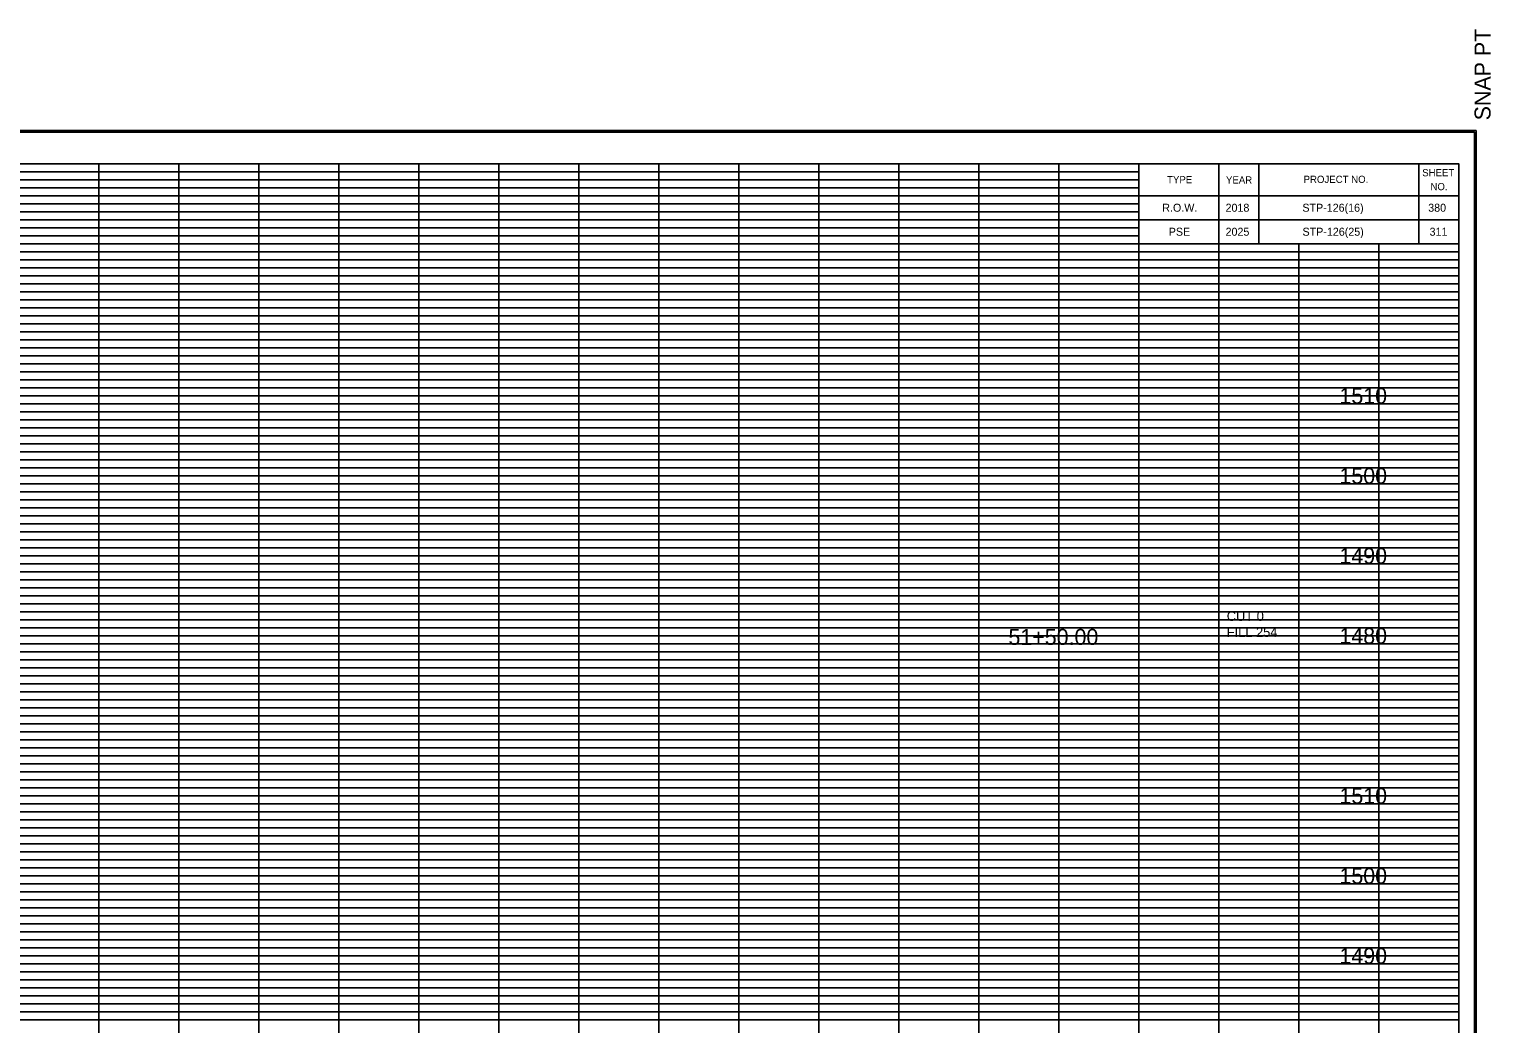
# Model space of a CAD drawing. Extents: x 980 to 1324, y 978 to 1497.
# Drawn here: x 1141.3 to 1324, y 1102.5 to 1226.8 of the extents above; entities that cross this region are included whole.
import ezdxf

# ---------------------------------------------------------------- set-up
doc = ezdxf.new("R2010")
doc.units = 0
for name, color, linetype in [('DESIGN - SCRATCH - User 1', 7, 'Continuous'), ('DESIGN - SHEET - Corner Text', 7, 'Continuous'), ('DESIGN - SHEET - Light Grid', 7, 'Continuous'), ('DESIGN - SHEET - Linework', 7, 'Continuous'), ('DESIGN - SHEET - Plot Shape', 7, 'Continuous'), ('DESIGN - TYPICAL - Text', 7, 'Continuous')]:
    doc.layers.add(name, color=color, linetype=linetype)

# ---------------------------------------------------------------- blocks, each defined once
blk = doc.blocks.new('XSTSHT')
at = {"layer": 'DESIGN - SCRATCH - User 1'}
for p, q in [((28.5, 20.45), (28.5, 20.45)), ((29.24, 20.45), (29.24, 20.45)), ((30.49, 20.45), (30.49, 20.45)), ((31.74, 20.45), (31.74, 20.45)), ((28.5, 20.15), (28.5, 20.15)), ((29.24, 20.15), (29.24, 20.15)), ((30.49, 20.15), (30.49, 20.15)), ((31.74, 20.15), (31.74, 20.15))]:
    blk.add_line(p, q, dxfattribs=at)
at = {"layer": 'DESIGN - SHEET - Light Grid'}
for p, q in [((8, 20.9), (16, 20.9)), ((16, 20.9), (24, 20.9)), ((24, 20.9), (28, 20.9)), ((8, 20.8), (16, 20.8)), ((8, 20.7), (16, 20.7)), ((16, 20.8), (24, 20.8)), ((16, 20.7), (24, 20.7)), ((24, 20.8), (28, 20.8)), ((24, 20.7), (28, 20.7)), ((8, 20.6), (16, 20.6)), ((8, 20.5), (16, 20.5)), ((16, 20.6), (24, 20.6)), ((16, 20.5), (24, 20.5)), ((24, 20.6), (28, 20.6)), ((24, 20.5), (28, 20.5)), ((8, 20.4), (16, 20.4)), ((8, 20.3), (16, 20.3)), ((16, 20.4), (24, 20.4)), ((16, 20.3), (24, 20.3)), ((24, 20.4), (28, 20.4)), ((24, 20.3), (28, 20.3)), ((8, 20.2), (16, 20.2)), ((8, 20.1), (16, 20.1)), ((16, 20.2), (24, 20.2)), ((16, 20.1), (24, 20.1)), ((24, 20.2), (28, 20.2)), ((24, 20.1), (28, 20.1)), ((8, 19.9), (16, 19.9)), ((8, 19.8), (16, 19.8)), ((16, 19.9), (24, 19.9)), ((16, 19.8), (24, 19.8)), ((24, 19.9), (32, 19.9)), ((24, 19.8), (32, 19.8)), ((8, 19.7), (16, 19.7)), ((8, 19.6), (16, 19.6)), ((16, 19.7), (24, 19.7)), ((16, 19.6), (24, 19.6)), ((24, 19.7), (32, 19.7)), ((24, 19.6), (32, 19.6)), ((8, 19.5), (16, 19.5)), ((8, 19.4), (16, 19.4)), ((16, 19.5), (24, 19.5)), ((16, 19.4), (24, 19.4)), ((24, 19.5), (32, 19.5)), ((24, 19.4), (32, 19.4)), ((8, 19.3), (16, 19.3)), ((8, 19.2), (16, 19.2)), ((16, 19.3), (24, 19.3)), ((16, 19.2), (24, 19.2)), ((24, 19.3), (32, 19.3)), ((24, 19.2), (32, 19.2)), ((8, 19.1), (16, 19.1)), ((16, 19.1), (24, 19.1)), ((24, 19.1), (32, 19.1)), ((8, 18.9), (16, 18.9)), ((16, 18.9), (24, 18.9)), ((24, 18.9), (32, 18.9)), ((8, 18.8), (16, 18.8)), ((8, 18.7), (16, 18.7)), ((16, 18.8), (24, 18.8)), ((16, 18.7), (24, 18.7)), ((24, 18.8), (32, 18.8)), ((24, 18.7), (32, 18.7)), ((8, 18.6), (16, 18.6)), ((8, 18.5), (16, 18.5)), ((16, 18.6), (24, 18.6)), ((16, 18.5), (24, 18.5)), ((24, 18.6), (32, 18.6)), ((24, 18.5), (32, 18.5)), ((8, 18.4), (16, 18.4)), ((8, 18.3), (16, 18.3)), ((16, 18.4), (24, 18.4)), ((16, 18.3), (24, 18.3)), ((24, 18.4), (32, 18.4)), ((24, 18.3), (32, 18.3)), ((8, 18.2), (16, 18.2)), ((8, 18.1), (16, 18.1)), ((16, 18.2), (24, 18.2)), ((16, 18.1), (24, 18.1)), ((24, 18.2), (32, 18.2)), ((24, 18.1), (32, 18.1)), ((8, 17.9), (16, 17.9)), ((8, 17.8), (16, 17.8)), ((16, 17.9), (24, 17.9)), ((16, 17.8), (24, 17.8)), ((24, 17.9), (32, 17.9)), ((24, 17.8), (32, 17.8)), ((8, 17.7), (16, 17.7)), ((8, 17.6), (16, 17.6)), ((16, 17.7), (24, 17.7)), ((16, 17.6), (24, 17.6)), ((24, 17.7), (32, 17.7)), ((24, 17.6), (32, 17.6)), ((8, 17.5), (16, 17.5)), ((8, 17.4), (16, 17.4)), ((16, 17.5), (24, 17.5)), ((16, 17.4), (24, 17.4)), ((24, 17.5), (32, 17.5)), ((24, 17.4), (32, 17.4)), ((8, 17.3), (16, 17.3)), ((8, 17.2), (16, 17.2)), ((16, 17.3), (24, 17.3)), ((16, 17.2), (24, 17.2)), ((24, 17.3), (32, 17.3)), ((24, 17.2), (32, 17.2)), ((8, 17.1), (16, 17.1)), ((16, 17.1), (24, 17.1)), ((24, 17.1), (32, 17.1)), ((8, 16.9), (16, 16.9)), ((16, 16.9), (24, 16.9)), ((24, 16.9), (32, 16.9)), ((8, 16.8), (16, 16.8)), ((8, 16.7), (16, 16.7)), ((16, 16.8), (24, 16.8)), ((16, 16.7), (24, 16.7)), ((24, 16.8), (32, 16.8)), ((24, 16.7), (32, 16.7)), ((8, 16.6), (16, 16.6)), ((8, 16.5), (16, 16.5)), ((16, 16.6), (24, 16.6)), ((16, 16.5), (24, 16.5)), ((24, 16.6), (32, 16.6)), ((24, 16.5), (32, 16.5)), ((8, 16.4), (16, 16.4)), ((8, 16.3), (16, 16.3)), ((16, 16.4), (24, 16.4)), ((16, 16.3), (24, 16.3)), ((24, 16.4), (32, 16.4)), ((24, 16.3), (32, 16.3)), ((8, 16.2), (16, 16.2)), ((8, 16.1), (16, 16.1)), ((16, 16.2), (24, 16.2)), ((16, 16.1), (24, 16.1)), ((24, 16.2), (32, 16.2)), ((24, 16.1), (32, 16.1)), ((8, 15.9), (16, 15.9)), ((16, 15.9), (24, 15.9)), ((24, 15.9), (32, 15.9)), ((8, 15.8), (16, 15.8)), ((16, 15.8), (24, 15.8)), ((24, 15.8), (32, 15.8)), ((8, 15.7), (16, 15.7)), ((8, 15.6), (16, 15.6)), ((16, 15.7), (24, 15.7)), ((16, 15.6), (24, 15.6)), ((24, 15.7), (32, 15.7)), ((24, 15.6), (32, 15.6)), ((8, 15.5), (16, 15.5)), ((8, 15.4), (16, 15.4)), ((16, 15.5), (24, 15.5)), ((16, 15.4), (24, 15.4)), ((24, 15.5), (32, 15.5)), ((24, 15.4), (32, 15.4)), ((8, 15.3), (16, 15.3)), ((8, 15.2), (16, 15.2)), ((16, 15.3), (24, 15.3)), ((16, 15.2), (24, 15.2)), ((24, 15.3), (32, 15.3)), ((24, 15.2), (32, 15.2)), ((8, 15.1), (16, 15.1)), ((16, 15.1), (24, 15.1)), ((24, 15.1), (32, 15.1)), ((8, 14.9), (16, 14.9)), ((8, 14.8), (16, 14.8)), ((16, 14.9), (24, 14.9)), ((16, 14.8), (24, 14.8)), ((24, 14.9), (32, 14.9)), ((24, 14.8), (32, 14.8)), ((8, 14.7), (16, 14.7)), ((16, 14.7), (24, 14.7)), ((24, 14.7), (32, 14.7)), ((8, 14.6), (16, 14.6)), ((8, 14.5), (16, 14.5)), ((16, 14.6), (24, 14.6)), ((16, 14.5), (24, 14.5)), ((24, 14.6), (32, 14.6)), ((24, 14.5), (32, 14.5)), ((8, 14.4), (16, 14.4)), ((8, 14.3), (16, 14.3)), ((16, 14.4), (24, 14.4)), ((16, 14.3), (24, 14.3)), ((24, 14.4), (32, 14.4)), ((24, 14.3), (32, 14.3)), ((8, 14.2), (16, 14.2)), ((8, 14.1), (16, 14.1)), ((16, 14.2), (24, 14.2)), ((16, 14.1), (24, 14.1)), ((24, 14.2), (32, 14.2)), ((24, 14.1), (32, 14.1)), ((8, 13.9), (16, 13.9)), ((16, 13.9), (24, 13.9)), ((24, 13.9), (32, 13.9)), ((8, 13.8), (16, 13.8)), ((16, 13.8), (24, 13.8)), ((24, 13.8), (32, 13.8)), ((8, 13.7), (16, 13.7)), ((8, 13.6), (16, 13.6)), ((16, 13.7), (24, 13.7)), ((16, 13.6), (24, 13.6)), ((24, 13.7), (32, 13.7)), ((24, 13.6), (32, 13.6)), ((8, 13.5), (16, 13.5)), ((8, 13.4), (16, 13.4)), ((16, 13.5), (24, 13.5)), ((16, 13.4), (24, 13.4)), ((24, 13.5), (32, 13.5)), ((24, 13.4), (32, 13.4)), ((8, 13.3), (16, 13.3)), ((8, 13.2), (16, 13.2)), ((16, 13.3), (24, 13.3)), ((16, 13.2), (24, 13.2)), ((24, 13.3), (32, 13.3)), ((24, 13.2), (32, 13.2)), ((8, 13.1), (16, 13.1)), ((16, 13.1), (24, 13.1)), ((24, 13.1), (32, 13.1)), ((8, 12.9), (16, 12.9)), ((8, 12.8), (16, 12.8)), ((16, 12.9), (24, 12.9)), ((16, 12.8), (24, 12.8)), ((24, 12.9), (32, 12.9)), ((24, 12.8), (32, 12.8)), ((8, 12.7), (16, 12.7)), ((16, 12.7), (24, 12.7)), ((24, 12.7), (32, 12.7)), ((8, 12.6), (16, 12.6)), ((8, 12.5), (16, 12.5)), ((16, 12.6), (24, 12.6)), ((16, 12.5), (24, 12.5)), ((24, 12.6), (32, 12.6)), ((24, 12.5), (32, 12.5)), ((8, 12.4), (16, 12.4)), ((8, 12.3), (16, 12.3)), ((16, 12.4), (24, 12.4)), ((16, 12.3), (24, 12.3)), ((24, 12.4), (32, 12.4)), ((24, 12.3), (32, 12.3)), ((8, 12.2), (16, 12.2)), ((8, 12.1), (16, 12.1)), ((16, 12.2), (24, 12.2)), ((16, 12.1), (24, 12.1)), ((24, 12.2), (32, 12.2)), ((24, 12.1), (32, 12.1)), ((8, 11.9), (16, 11.9)), ((16, 11.9), (24, 11.9)), ((24, 11.9), (32, 11.9)), ((8, 11.8), (16, 11.8)), ((8, 11.7), (16, 11.7)), ((16, 11.8), (24, 11.8)), ((16, 11.7), (24, 11.7)), ((24, 11.8), (32, 11.8)), ((24, 11.7), (32, 11.7)), ((8, 11.6), (16, 11.6)), ((16, 11.6), (24, 11.6)), ((24, 11.6), (32, 11.6)), ((8, 11.5), (16, 11.5)), ((8, 11.4), (16, 11.4)), ((16, 11.5), (24, 11.5)), ((16, 11.4), (24, 11.4)), ((24, 11.5), (32, 11.5)), ((24, 11.4), (32, 11.4)), ((8, 11.3), (16, 11.3)), ((8, 11.2), (16, 11.2)), ((16, 11.3), (24, 11.3)), ((16, 11.2), (24, 11.2)), ((24, 11.3), (32, 11.3)), ((24, 11.2), (32, 11.2)), ((8, 11.1), (16, 11.1)), ((16, 11.1), (24, 11.1)), ((24, 11.1), (32, 11.1)), ((8, 10.9), (16, 10.9)), ((8, 10.8), (16, 10.8)), ((16, 10.9), (24, 10.9)), ((16, 10.8), (24, 10.8)), ((24, 10.9), (32, 10.9)), ((24, 10.8), (32, 10.8)), ((8, 10.7), (16, 10.7)), ((8, 10.6), (16, 10.6)), ((16, 10.7), (24, 10.7)), ((16, 10.6), (24, 10.6)), ((24, 10.7), (32, 10.7)), ((24, 10.6), (32, 10.6)), ((8, 10.5), (16, 10.5)), ((16, 10.5), (24, 10.5)), ((24, 10.5), (32, 10.5)), ((8, 10.4), (16, 10.4)), ((8, 10.3), (16, 10.3)), ((16, 10.4), (24, 10.4)), ((16, 10.3), (24, 10.3)), ((24, 10.4), (32, 10.4)), ((24, 10.3), (32, 10.3))]:
    blk.add_line(p, q, dxfattribs=at)
at = {"layer": 'DESIGN - SHEET - Linework'}
for p, q in [((-1.823, 21.414), (32.217, 21.414)), ((32.217, 21.414), (32.217, -0.414)), ((15, 0), (15, 21)), ((16, 0), (16, 21)), ((17, 0), (17, 21)), ((18, 0), (18, 21)), ((19, 0), (19, 21)), ((20, 0), (20, 21)), ((21, 0), (21, 21)), ((22, 0), (22, 21)), ((23, 0), (23, 21)), ((24, 0), (24, 21)), ((25, 0), (25, 21)), ((26, 0), (26, 21)), ((27, 0), (27, 21)), ((0, 20), (28, 20)), ((28, 0), (28, 20)), ((29, 0), (29, 20)), ((30, 0), (30, 20)), ((31, 0), (31, 20)), ((0, 19), (32, 19)), ((0, 18), (32, 18)), ((0, 17), (32, 17)), ((0, 16), (32, 16)), ((0, 15), (32, 15)), ((0, 14), (32, 14)), ((0, 13), (32, 13)), ((0, 12), (32, 12)), ((0, 11), (32, 11))]:
    blk.add_line(p, q, dxfattribs=at)
for points in [[(0, 21), (0, 0), (32, 0), (32, 21), (0, 21)], [(28, 21), (28, 20), (32, 20), (32, 21), (31.5, 21), (31.5, 20), (29.5, 20), (29.5, 21), (29, 21), (29, 20), (32, 20), (28, 20), (28, 20.3), (32, 20.3), (32, 20.6), (28, 20.6)]]:
    blk.add_lwpolyline(points, dxfattribs=at)
at = {"layer": 'DESIGN - SHEET - Plot Shape'}
for points in [[(-1.803, 21.394), (32.197, 21.394), (32.197, -0.394), (-1.803, -0.394)], [(-0.85, 21), (32, 21), (32, -0.25), (-0.85, -0.25)]]:
    blk.add_lwpolyline(points, close=True, dxfattribs=at)
at = {"layer": 'DESIGN - SHEET - Corner Text'}
blk.add_text('  SNAP PT', height=0.2, rotation=90, dxfattribs=at).set_placement((32.397, 21.394))
for s, p in [('TYPE', (28.354, 20.756)), ('YEAR', (29.09, 20.752)), ('PROJECT NO.', (30.06, 20.76)), ('SHEET', (31.543, 20.843)), ('NO.', (31.646, 20.669))]:
    blk.add_text(s, height=0.09, dxfattribs=at).set_placement(p)

msp = doc.modelspace()

# ---------------------------------------------------------------- linework, layer by layer
at = {"layer": 'DESIGN - SHEET - Plot Shape'}
msp.add_lwpolyline([(991.5, 997.5), (1320, 997.5), (1320, 1210), (991.5, 1210)], close=True, dxfattribs=at)

# ---------------------------------------------------------------- block references
at = {"layer": 'DESIGN - TYPICAL - Text', "xscale": 10, "yscale": 10}
msp.add_blockref('XSTSHT', (1000, 1000), dxfattribs=at)

# ---------------------------------------------------------------- texts
at = {"layer": 'DESIGN - SHEET - Corner Text'}
for s, p in [('R.O.W.', (1282.94, 1204)), ('2018', (1290.85, 1204)), ('STP-126(16)', (1300.45, 1204)), ('380', (1316.18, 1204)), ('STP-126(25)', (1300.47, 1201)), ('PSE', (1283.75, 1201)), ('2025', (1290.85, 1201)), ('311', (1316.35, 1201))]:
    msp.add_text(s, height=1, dxfattribs=at).set_placement(p)
at = {"layer": 'DESIGN - TYPICAL - Text'}
for s, height, p in [('     1510     ', 2, (1301.37, 1180)), ('     1500     ', 2, (1301.37, 1170)), ('     1490     ', 2, (1301.37, 1160)), ('CUT 0', 1.2, (1291, 1152.86)), ('     51+50.00     ', 2, (1260, 1149.86)), ('FILL 254', 1.2, (1291, 1150.86)), ('     1480     ', 2, (1301.37, 1150)), ('     1510     ', 2, (1301.37, 1130)), ('     1500     ', 2, (1301.37, 1120)), ('     1490     ', 2, (1301.37, 1110))]:
    msp.add_text(s, height=height, dxfattribs=at).set_placement(p)

doc.saveas('drawing.dxf')
